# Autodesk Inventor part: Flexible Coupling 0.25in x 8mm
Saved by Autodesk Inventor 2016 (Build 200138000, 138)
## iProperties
Created: 2016-01
Part Number: Flexible Coupling 0.25in x 8mm
Material: Generic
Document SubType Name: Modeling
Designer: John
Density: 1 g/cm^3
Appearance: Default
Author: John
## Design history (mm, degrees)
feature "CHAMFER1"
body "Solid1"
